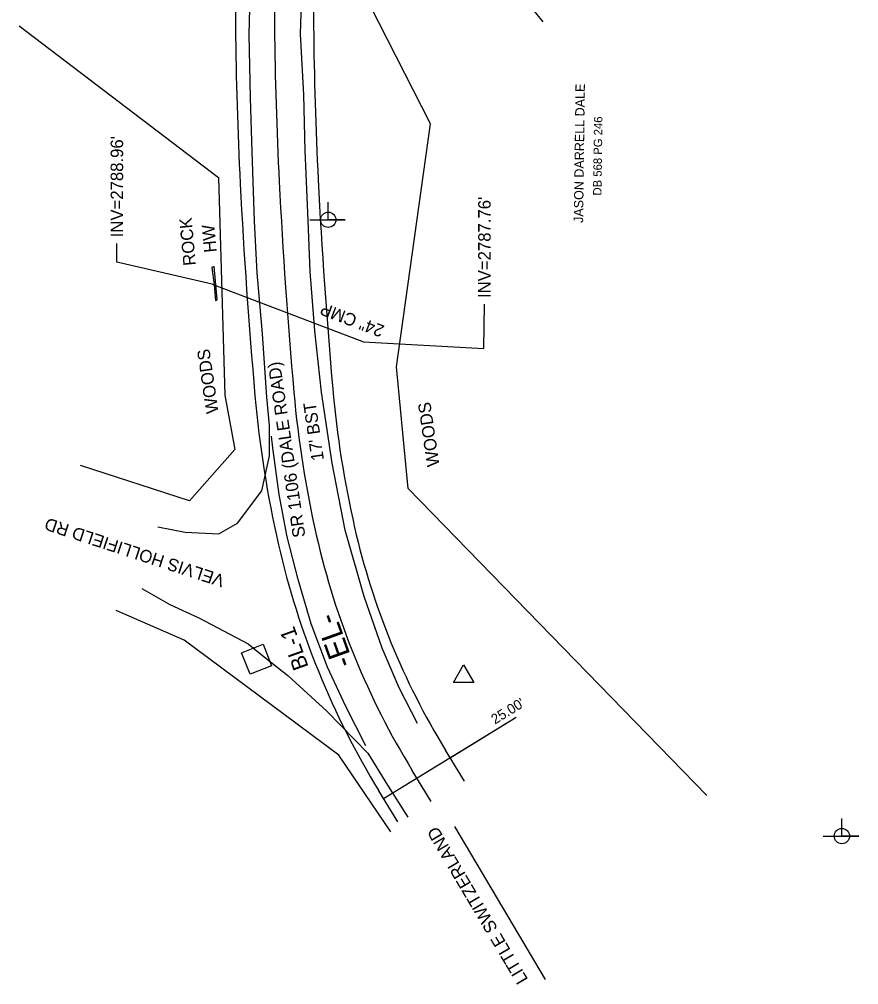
# Model space of a CAD drawing. Extents: x 1088366 to 1089341, y 781245 to 782648.
# Drawn here: x 1088772.6 to 1089041.3, y 781245.5 to 781554.6 of the extents above; entities that cross this region are included whole.
import ezdxf

# ---------------------------------------------------------------- set-up
doc = ezdxf.new("R2010")
doc.units = 0
for name, color, linetype in [('CTL Secondary Horizontal and Vertical CELL', 7, 'Continuous'), ('CTL Secondary Horizontal and Vertical Text', 7, 'Continuous'), ('Exist Horizontal Alignment', 7, 'Continuous'), ('Exist Horizontal Alignment Direction Label', 7, 'Continuous'), ('Exist Property Deed Book Text', 7, 'Continuous'), ('Exist Property Owner Text', 7, 'Continuous'), ('Exist Right of Way Line', 7, 'Continuous'), ('Exist Right of Way Monument CELL', 7, 'Continuous'), ('Exist Right of Way Width CELL', 7, 'Continuous'), ('Exist Roads EOP', 7, 'Continuous'), ('Exist Roads EOP Leader', 7, 'Continuous'), ('Exist Roads EOP Text', 7, 'Continuous'), ('Exist Roads EOT', 7, 'Continuous'), ('Exist Structure Minor Head and End Wall', 7, 'Continuous'), ('Exist Structure Minor Head and End Wall Text', 7, 'Continuous'), ('Exist Structure Minor Pipes CMP 24 Inch', 7, 'Continuous'), ('Exist Structure Minor Pipes CMP 24 Inch Invert', 7, 'Continuous'), ('Exist Structure Minor Pipes CMP 24 Inch Leader', 7, 'Continuous'), ('Exist Structure Minor Pipes CMP 24 Inch Text', 7, 'Continuous'), ('Exist Utilities Power Joint Use Telephone CELL', 7, 'Continuous'), ('Exist Vegetation Woods Line', 7, 'Continuous'), ('Exist Vegetation Woods Line Text', 7, 'Continuous')]:
    doc.layers.add(name, color=color, linetype=linetype)

msp = doc.modelspace()

# ---------------------------------------------------------------- linework, layer by layer
at = {"layer": 'CTL Secondary Horizontal and Vertical CELL'}
msp.add_line((1088848.51, 781349.68), (1088848.51, 781349.68), dxfattribs=at)
msp.add_lwpolyline([(1088843.74, 781351.78), (1088850.64, 781354.48), (1088853.35, 781347.57), (1088846.45, 781344.87)], close=True, dxfattribs=at)
at = {"layer": 'Exist Horizontal Alignment'}
msp.add_line((1088904.47, 781304.15), (1088898.38, 781314.07), dxfattribs=at)
for centre, radius, start, end in [((1090054.25, 781563.48), 1200, 178.16512, 182.91094), ((1090657.47, 781594.16), 1804, 182.91094, 185.0565), ((1089201.09, 781465.29), 341.93, 185.0565, 192.8745), ((1089111.47, 781444.81), 250, 192.8745, 211.5313)]:
    msp.add_arc(centre, radius, start, end, dxfattribs=at)
at = {"layer": 'Exist Right of Way Line'}
for p, q in [((1088915.12, 781310.69), (1088909.04, 781320.61)), ((1088893.81, 781297.62), (1088887.73, 781307.53))]:
    msp.add_line(p, q, dxfattribs=at)
for centre, radius, start, end in [((1090054.25, 781563.48), 1212.5, 178.16512, 182.91094), ((1090054.25, 781563.48), 1187.5, 178.16512, 182.91094), ((1090657.47, 781594.16), 1791.5, 182.91094, 185.0565), ((1090657.47, 781594.16), 1816.5, 182.91094, 185.0565), ((1089201.09, 781465.29), 329.43, 185.0565, 192.8745), ((1089201.09, 781465.29), 354.43, 185.0565, 192.8745), ((1089111.47, 781444.81), 237.5, 192.8745, 211.5313), ((1089111.47, 781444.81), 262.5, 192.8745, 211.5313)]:
    msp.add_arc(centre, radius, start, end, dxfattribs=at)
at = {"layer": 'Exist Right of Way Monument CELL'}
msp.add_line((1088914.82, 781344.14), (1088914.82, 781344.14), dxfattribs=at)
msp.add_lwpolyline([(1088911.57, 781342.25), (1088914.82, 781347.89), (1088918.07, 781342.25)], close=True, dxfattribs=at)
at = {"layer": 'Exist Right of Way Width CELL'}
for p in [(1088889.23, 781305.08), (1088910.54, 781318.16)]:
    msp.add_line(p, (1088931.67, 781331.13), dxfattribs=at)
at = {"layer": 'Exist Roads EOP'}
for points in [[(1088816.98, 781392.1), (1088825.71, 781390.34), (1088836.51, 781389.83), (1088842.4, 781393.21), (1088850.19, 781403.57), (1088852.65, 781414.78), (1088852.65, 781424.49), (1088851.88, 781433.63), (1088850.48, 781453.88), (1088848.69, 781473.37), (1088847.88, 781489.94), (1088847.11, 781512.12), (1088846.64, 781529.44), (1088846.17, 781549.67), (1088846.62, 781566.42), (1088846.42, 781593.45), (1088846.98, 781618.23), (1088847.64, 781636.22), (1088848.28, 781653.61), (1088848.31, 781666.83)], [(1088900.09, 781329.12), (1088894.18, 781340.49), (1088888.72, 781353.18), (1088882.98, 781369.77), (1088876.9, 781391.05), (1088872.78, 781412.4), (1088869.35, 781435.21), (1088867.18, 781454.87), (1088865.69, 781473.85), (1088865.05, 781490.1), (1088864.15, 781512.52), (1088863.65, 781530.36), (1088862.62, 781549.93), (1088863.18, 781566.19), (1088863.57, 781593.2), (1088863.38, 781617.88), (1088863.57, 781636.34), (1088864.04, 781656.78)], [(1088811.81, 781372.37), (1088820.76, 781367.24), (1088830.03, 781362.98), (1088845.84, 781354.66), (1088852.09, 781349.64), (1088858.57, 781344.5), (1088871, 781333.02), (1088884.13, 781319.62), (1088890.52, 781309.32), (1088896.96, 781299.07)]]:
    msp.add_lwpolyline(points, dxfattribs=at)
at = {"layer": 'Exist Roads EOP Leader'}
msp.add_line((1088941.01, 781247.15), (1088912.02, 781296.12), dxfattribs=at)
at = {"layer": 'Exist Roads EOT'}
msp.add_lwpolyline([(1088883.53, 781321.99), (1088877.08, 781334.51), (1088871.3, 781347.14), (1088866.08, 781361.05), (1088861.92, 781375.23), (1088858.33, 781388.82), (1088855.74, 781402.39), (1088853.73, 781417.35), (1088853.37, 781421.14)], dxfattribs=at)
at = {"layer": 'Exist Structure Minor Head and End Wall'}
msp.add_lwpolyline([(1088835.36, 781464.52), (1088835.93, 781464.85), (1088835.02, 781475.38), (1088834.21, 781475.13), (1088834.96, 781469.56), (1088835.36, 781464.52)], dxfattribs=at)
at = {"layer": 'Exist Structure Minor Pipes CMP 24 Inch'}
msp.add_line((1088834.32, 781469.72), (1088882.74, 781451.34), dxfattribs=at)
at = {"layer": 'Exist Structure Minor Pipes CMP 24 Inch Leader'}
for points in [[(1088834.32, 781469.72), (1088803.83, 781476.76), (1088803.83, 781482.76)], [(1088882.74, 781451.34), (1088921.3, 781449.2), (1088921.5, 781463.34)]]:
    msp.add_lwpolyline(points, dxfattribs=at)
at = {"layer": 'Exist Utilities Power Joint Use Telephone CELL'}
for p, q in [((1088871.51, 781490.38), (1088871.51, 781490.38)), ((1089035.94, 781293.06), (1089035.94, 781293.06))]:
    msp.add_line(p, q, dxfattribs=at)
for points in [[(1088865.57, 781490.38), (1088876.91, 781490.34), (1088871.51, 781490.36), (1088871.51, 781496)], [(1089030, 781293.06), (1089041.33, 781293.03), (1089035.94, 781293.04), (1089035.94, 781298.69)]]:
    msp.add_lwpolyline(points, dxfattribs=at)
for centre in [(1088871.51, 781490.38), (1089035.94, 781293.07)]:
    msp.add_circle(centre, 2.45, dxfattribs=at)
at = {"layer": 'Exist Vegetation Woods Line'}
for points in [[(1088992.73, 781306.05), (1088897.1, 781404.36), (1088893.35, 781443.24), (1088904.2, 781521.06), (1088876.71, 781575.21), (1088876.03, 781632.36), (1088940.16, 781553.71)], [(1088772.59, 781552.44), (1088836.33, 781503.92), (1088838.38, 781434.17), (1088841.62, 781416.79), (1088827.05, 781400.38), (1088792.19, 781411.73)], [(1088891.55, 781294.47), (1088874.85, 781318.99), (1088857.34, 781332.01), (1088825.33, 781355.8), (1088803.62, 781365.32)]]:
    msp.add_lwpolyline(points, dxfattribs=at)

# ---------------------------------------------------------------- texts
at = {"layer": 'CTL Secondary Horizontal and Vertical Text'}
msp.add_text('BL-1', height=5, rotation=109.6575, dxfattribs=at).set_placement((1088865.26, 781347.26))
at = {"layer": 'Exist Horizontal Alignment Direction Label'}
msp.add_text('-EL-', height=7, rotation=109.6575, dxfattribs=at).set_placement((1088879.67, 781348.32))
at = {"layer": 'Exist Property Deed Book Text'}
msp.add_text('DB 568 PG 246', height=2.7, rotation=89.2651, dxfattribs=at).set_placement((1088958.97, 781498.13))
at = {"layer": 'Exist Property Owner Text'}
msp.add_text('JASON DARRELL DALE', height=3, rotation=89.2651, dxfattribs=at).set_placement((1088953.1, 781489.35))
at = {"layer": 'Exist Right of Way Width CELL'}
msp.add_text("25.00'", height=3.2, rotation=31.5313, dxfattribs=at).set_placement((1088924.88, 781328.75))
at = {"layer": 'Exist Roads EOP Text'}
for s, rotation, p in [('SR 1106 (DALE ROAD)', 98.2653, (1088864.2, 781388.95)), ("17' BST", 98.2653, (1088870.14, 781413.52)), ('VELVIS HOLLIFIELD RD', 161.9385, (1088838.62, 781376.47)), ('LITTLE SWITZERLAND', 120.6547, (1088935.6, 781247.15))]:
    msp.add_text(s, height=4, rotation=rotation, dxfattribs=at).set_placement(p)
at = {"layer": 'Exist Structure Minor Head and End Wall Text'}
for s, p in [('ROCK', (1088829.16, 781475.85)), ('HW', (1088835.8, 781480.07))]:
    msp.add_text(s, height=4, rotation=95.2865, dxfattribs=at).set_placement(p)
at = {"layer": 'Exist Structure Minor Pipes CMP 24 Inch Invert'}
for s, p in [("INV=2788.96'", (1088805.83, 781484.76)), ("INV=2787.76'", (1088923.5, 781465.34))]:
    msp.add_text(s, height=4, rotation=90, dxfattribs=at).set_placement(p)
at = {"layer": 'Exist Structure Minor Pipes CMP 24 Inch Text'}
msp.add_text('24" CMP', height=4, rotation=159.2073, dxfattribs=at).set_placement((1088889.76, 781456.37))
at = {"layer": 'Exist Vegetation Woods Line Text'}
for p in [(1088836.43, 781428.64), (1088907.15, 781411.64)]:
    msp.add_text('WOODS', height=4, rotation=98.2653, dxfattribs=at).set_placement(p)

doc.saveas('drawing.dxf')
